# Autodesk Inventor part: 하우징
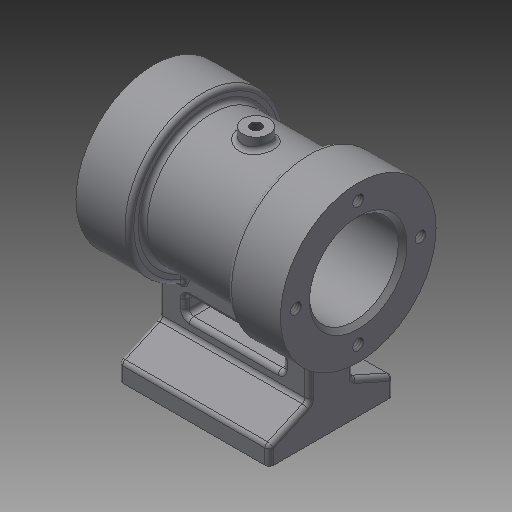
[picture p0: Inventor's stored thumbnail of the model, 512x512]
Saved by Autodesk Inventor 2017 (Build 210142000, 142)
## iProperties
Created: 2018-01
Part Number: 하우징
Material: 알루미늄 6061
Document SubType Name: Modeling
Designer: mduedu
Density: 2.71 g/cm^3
Mass: 86.5108 g
Surface Area: 128.667 cm^2
Volume: 31.9228 cm^3
Appearance: 기본값
Author: mduedu
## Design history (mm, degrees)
sketch "스케치1"
  geometry: L1 (-23, 0)-(23, 0); L2 (-23, 0)-(-23, 17.5); L3 (-23, 17.5)-(-11, 17.5); L4 (-11, 17.5)-(-11, 14.5); L5 (-11, 14.5)-(11, 14.5); L6 (11, 14.5)-(11, 17.5); L7 (11, 17.5)-(23, 17.5); L8 (23, 17.5)-(23, 0); 2 further points
  constraints: 16 end point, 3 parallel, 2 collinear, 2 perpendicular, 1 coincident, 1 horizontal, 1 midpoint, 1 vertical
  dimensions: "d0" = 46 distance of L1.start L1.end; "d2" = 12 distance of L2.end L3.end; "d3" = 12 distance of L6.end L7.end (= d2); "d4" = 35 diameter of L3 L1; "d5" = 29 diameter of L5 L1
revolve "회전1" sketch "스케치1" stored, may be unused: angle "d6" = 90 deg
hole "구멍1" diameter "d9" = 20; stored, may be unused: countersink angle "d13" = 90 deg, drill point angle "d15" = 118 deg; dims "d7" = 10, "d8" = 10, "d10" = 6, "d11" = 4, "d12" = 2, "d14" = 8
fillet "모깎기1" dims "d16" = 1
sketch "스케치2"
  geometry: L1 (0, 0)-(-34, 0); L2 (-34, 14)-(-34, -14); L3 (-34, 14)-(-30, 14); L4 (-30, 14)-(-26, 5); L5 (-26, 5)-(-13.611, 5); L6 (-26, -5)-(-13.611, -5); L7 (-30, -14)-(-26, -5); L8 (-34, -14)-(-30, -14); C1 r 10 at (0, 0) reference; A1 r 14.5 centre (0, 0) between (-13.611, 5) and (-13.611, -5); 2 further points
  constraints: 16 end point, 3 symmetric about line, 2 perpendicular, 2 point on circle, 1 centre point, 1 coincident, 1 horizontal, 1 midpoint, 1 parallel, 2 other
  dimensions: "d17" = 34 distance of L1.end L1.start; "d18" = 28 distance between parallel lines of L8 L3; "d19" = 10 distance between parallel lines of L6 L5; "d20" = 4 distance of L2.end L7.start; "d21" = 8 distance from line of L6.start L2
extrude "돌출1" join sketch "스케치2" stored distance "d22" = 34; taper "d23" = 0 deg
sketch "스케치3"
  geometry: L1 (-11, -19)-(11, -19); L2 (11, -19)-(11, -23); L3 (11, -23)-(-11, -23); L4 (-11, -23)-(-11, -19); L5 (-17, -16.771)-(-17, -26) reference; L6 (17, -26)-(17, -16.771) reference; L7 (-17, -34)-(17, -34) reference; 1 further point
  constraints: 8 end point, 2 parallel, 1 horizontal, 1 perpendicular
  dimensions: "d24" = 6 distance between parallel lines of L4 L5; "d25" = 6 distance between parallel lines of L2 L6; "d26" = 11 distance between parallel lines of L3 L7; "d27" = 4 distance of L1.end L2.end
extrude "돌출2" cut sketch "스케치3" stored distance "d28" = 34; taper "d29" = 0 deg
fillet "모깎기2" dims "d30" = 1
fillet "모깎기3" dims "d31" = 1
fillet "모깎기4" dims "d32" = 1
fillet "모깎기5" dims "d33" = 1
fillet "모깎기6" dims "d34" = 1
sketch "스케치4" dims "d7" = 10, "d8" = 10
  geometry: C1 r 17.5 at (0, 0) reference; A1 r 14 centre (0, 0) between (0, 14) and (-14, 0); 2 further points
  constraints: 4 point on circle, 2 horizontal alignment, 2 vertical alignment, 1 centre point, 1 coincident
  dimensions: "d75" = 28 diameter of A1
hole "구멍2" sketch "스케치4" at (-14, 0), (0, -14), (14, 0), (0, 14) diameter "d35" = 2.459; stored, may be unused: countersink angle "d39" = 90 deg, drill point angle "d41" = 120 deg; dims "d36" = 5.5, "d37" = 4, "d38" = 2, "d40" = 7
sketch "스케치5"
  geometry: A1 r 17.5 centre (0, 0) between (5.676, -16.554) and (-5.676, -16.554) reference; A2 r 14 centre (0, 0) between (0, 14) and (14, 0); 2 further points
  constraints: 4 point on circle, 2 horizontal alignment, 2 vertical alignment, 1 centre point, 1 coincident
  dimensions: "d80" = 28 diameter of A2
hole "구멍4" sketch "스케치5" at (-14, 0), (0, -14), (14, 0), (0, 14) diameter "d42" = 2.459; stored, may be unused: countersink angle "d46" = 90 deg, drill point angle "d48" = 120 deg; dims "d43" = 5.5, "d44" = 4, "d45" = 2, "d47" = 7
sketch "스케치6"
  geometry: 2 further points
  constraints: 2 other
hole "구멍5" sketch "스케치6" at (7, 14), (25, 14) diameter "d49" = 2.459; stored, may be unused: countersink angle "d53" = 90 deg, drill point angle "d55" = 120 deg; dims "d50" = 6, "d51" = 4, "d52" = 2, "d54" = 8
node "작업 평면1"
sketch "스케치7"
  geometry: L1 (-23, 17.5)-(-23, -17.5) reference; C1 r 3 at (0, 0); 1 further point
  constraints: 2 coincident, 1 centre point
  dimensions: "d57" = 6 diameter of C1
extrude "돌출3" join sketch "스케치7" stored distance "d61" = 10; taper "d62" = 0 deg
fillet "모깎기7" dims "d63" = 1
hole "구멍6" diameter "d66" = 2.459; stored, may be unused: countersink angle "d70" = 90 deg, drill point angle "d72" = 118 deg; dims "d64" = 10, "d65" = 10, "d67" = 6, "d68" = 4, "d69" = 2, "d71" = 8
chamfer "모따기1" distance "d77" = 1; stored, may be unused: second distance "d78" = 2, angle "d79" = 45 deg
node "솔리드1"
node "절단 모서리 투영1"
other parameters: "d56" = 17
